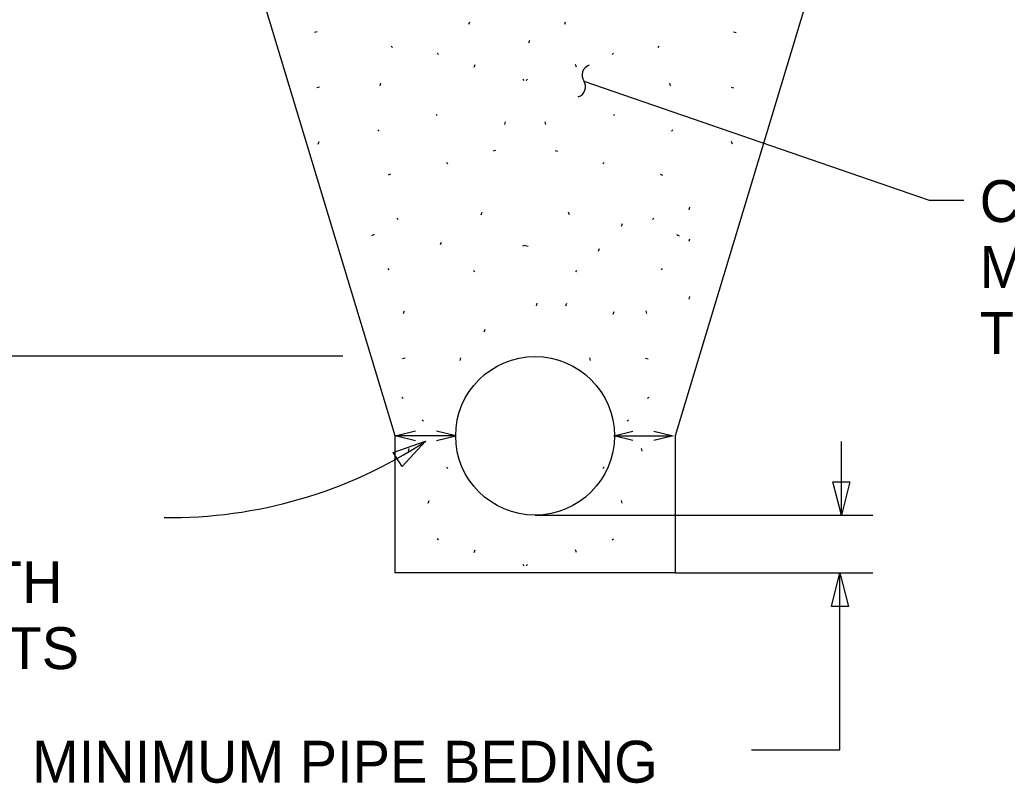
# Model space of a CAD drawing. Extents: x 9937.2 to 10006.2, y 10008.4 to 10068.3.
# Drawn here: x 9962.48 to 9987.09, y 10030.41 to 10049.44 of the extents above; entities that cross this region are included whole.
import ezdxf

# ---------------------------------------------------------------- set-up
doc = ezdxf.new("R2010")
doc.units = 0
for name, color, linetype in [('Default', 7, 'Continuous'), ('G-ANNO-TEXT', 7, 'Continuous'), ('G-ANNO-TTXT', 7, 'Continuous'), ('G-DETL-OTLN', 7, 'Continuous'), ('G-DETL-PATT', 7, 'Continuous')]:
    doc.layers.add(name, color=color, linetype=linetype)

# ---------------------------------------------------------------- blocks, each defined once
blk = doc.blocks.new('TERARR')
at = {"layer": 'Default'}
blk.add_lwpolyline([(-0.667, 0.167), (0, 0), (-0.667, -0.167)], close=True, dxfattribs=at)
blk = doc.blocks.new('TERBRK')
at = {"layer": 'Default'}
for centre, start, end in [((0.125, 0.167), 126.8699, 233.1301), ((-0.125, -0.167), 306.8699, 53.1301)]:
    blk.add_arc(centre, 0.208, start, end, dxfattribs=at)

msp = doc.modelspace()

# ---------------------------------------------------------------- linework, layer by layer
at = {"layer": 'Default'}
for p, q in [((9980.264, 10049.131), (9980.329, 10049.117)), ((9972.165, 10038.689), (9972.186, 10038.751)), ((9977.009, 10038.257), (9977.04, 10038.289))]:
    msp.add_line(p, q, dxfattribs=at)
at = {"layer": 'G-ANNO-TEXT'}
for p, q in [((9952.831, 10041.058), (9970.536, 10041.058)), ((9973.344, 10039.068), (9971.834, 10039.068)), ((9977.301, 10039.068), (9978.69, 10039.068)), ((9982.954, 10037.089), (9982.954, 10038.926)), ((9975.322, 10037.089), (9983.741, 10037.089)), ((9978.811, 10035.651), (9983.741, 10035.651)), ((9982.92, 10031.241), (9982.92, 10035.651)), ((9980.718, 10031.241), (9982.92, 10031.241))]:
    msp.add_line(p, q, dxfattribs=at)
for points in [[(9972.346, 10039.187), (9971.867, 10039.068), (9972.346, 10038.948)], [(9972.865, 10038.948), (9973.344, 10039.068), (9972.865, 10039.187)], [(9977.761, 10038.948), (9977.283, 10039.068), (9977.761, 10039.187)], [(9978.281, 10039.187), (9978.759, 10039.068), (9978.281, 10038.948)]]:
    msp.add_lwpolyline(points, dxfattribs=at)
msp.add_arc((9966.241, 10048.601), 11.569, 269.1889, 303.3244, dxfattribs=at)
at = {"layer": 'G-ANNO-TTXT'}
msp.add_lwpolyline([(9976.536, 10047.909), (9985.138, 10044.937), (9986.005, 10044.937)], dxfattribs=at)
at = {"layer": 'G-DETL-OTLN'}
msp.add_lwpolyline([(9984.004, 10056.263), (9978.811, 10039.068), (9978.811, 10035.651), (9971.834, 10035.651), (9971.834, 10039.068), (9966.641, 10056.263)], dxfattribs=at)
msp.add_circle((9975.322, 10039.068), 1.978, dxfattribs=at)
at = {"layer": 'G-DETL-PATT'}
for p, q in [((9973.673, 10049.322), (9973.694, 10049.385)), ((9976.063, 10049.322), (9976.084, 10049.385)), ((9969.894, 10049.131), (9969.829, 10049.117)), ((9975.167, 10048.86), (9975.188, 10048.923)), ((9971.772, 10048.743), (9971.74, 10048.774)), ((9978.386, 10048.743), (9978.418, 10048.774)), ((9972.915, 10048.567), (9972.883, 10048.599)), ((9977.243, 10048.567), (9977.275, 10048.599)), ((9973.805, 10048.258), (9973.826, 10048.321)), ((9976.353, 10048.258), (9976.332, 10048.321)), ((9975.054, 10047.924), (9975.023, 10047.955)), ((9975.104, 10047.924), (9975.135, 10047.955)), ((9969.953, 10047.756), (9969.888, 10047.742)), ((9971.461, 10047.79), (9971.482, 10047.853)), ((9978.697, 10047.79), (9978.676, 10047.853)), ((9980.205, 10047.756), (9980.27, 10047.742)), ((9972.885, 10047.047), (9972.854, 10047.078)), ((9977.273, 10047.047), (9977.304, 10047.078)), ((9971.437, 10046.661), (9971.406, 10046.692)), ((9974.567, 10046.825), (9974.588, 10046.888)), ((9975.591, 10046.825), (9975.57, 10046.888)), ((9978.721, 10046.661), (9978.752, 10046.692)), ((9969.919, 10046.338), (9969.94, 10046.401)), ((9980.239, 10046.338), (9980.218, 10046.401)), ((9974.338, 10046.177), (9974.274, 10046.163)), ((9975.82, 10046.177), (9975.884, 10046.163)), ((9973.149, 10045.848), (9973.118, 10045.879)), ((9977.009, 10045.848), (9977.04, 10045.879)), ((9971.721, 10045.592), (9971.658, 10045.561)), ((9978.437, 10045.592), (9978.5, 10045.561)), ((9979.16, 10044.703), (9979.181, 10044.765)), ((9971.909, 10044.461), (9971.878, 10044.493)), ((9973.981, 10044.574), (9974.002, 10044.637)), ((9976.177, 10044.574), (9976.156, 10044.637)), ((9978.249, 10044.461), (9978.28, 10044.493)), ((9977.476, 10044.295), (9977.497, 10044.358)), ((9971.311, 10044.084), (9971.248, 10044.053)), ((9978.847, 10044.084), (9978.91, 10044.053)), ((9979.16, 10043.915), (9979.181, 10043.977)), ((9972.967, 10043.833), (9972.988, 10043.896)), ((9975.071, 10043.809), (9975.006, 10043.795)), ((9975.087, 10043.809), (9975.152, 10043.795)), ((9976.905, 10043.67), (9976.926, 10043.733)), ((9971.689, 10043.205), (9971.658, 10043.236)), ((9978.469, 10043.205), (9978.5, 10043.236)), ((9973.823, 10043.158), (9973.792, 10043.189)), ((9976.335, 10043.158), (9976.366, 10043.189)), ((9979.16, 10042.474), (9979.181, 10042.537)), ((9975.357, 10042.311), (9975.378, 10042.374)), ((9976.091, 10042.311), (9976.112, 10042.374)), ((9972.047, 10042.117), (9972.068, 10042.18)), ((9977.268, 10042.099), (9977.289, 10042.162)), ((9978.111, 10042.117), (9978.09, 10042.18)), ((9974.054, 10041.659), (9974.075, 10041.722)), ((9972.082, 10041.002), (9972.017, 10040.988)), ((9973.453, 10040.948), (9973.474, 10041.011)), ((9976.705, 10040.948), (9976.684, 10041.011)), ((9978.076, 10041.002), (9978.141, 10040.988)), ((9972.035, 10040), (9972.004, 10040.031)), ((9978.123, 10040), (9978.154, 10040.031)), ((9972.539, 10039.434), (9972.508, 10039.466)), ((9977.619, 10039.434), (9977.65, 10039.466)), ((9977.993, 10038.689), (9977.972, 10038.751)), ((9973.149, 10038.257), (9973.118, 10038.289)), ((9972.662, 10037.392), (9972.683, 10037.455)), ((9977.496, 10037.392), (9977.475, 10037.455)), ((9972.915, 10036.474), (9972.883, 10036.505)), ((9977.243, 10036.474), (9977.275, 10036.505)), ((9973.805, 10036.164), (9973.826, 10036.227)), ((9976.353, 10036.164), (9976.332, 10036.227)), ((9975.054, 10035.83), (9975.023, 10035.862)), ((9975.104, 10035.83), (9975.135, 10035.862))]:
    msp.add_line(p, q, dxfattribs=at)

# ---------------------------------------------------------------- block references
at = {"layer": 'G-ANNO-TEXT'}
for p, xscale, yscale, rotation in [((9972.596, 10038.935), 1.2500000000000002, 1.2499999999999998, 33.32435277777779), ((9982.954, 10037.089), 1.25, 1.25, -90), ((9982.92, 10035.651), 1.25, 1.25, 90)]:
    msp.add_blockref('TERARR', p, dxfattribs=dict(at, xscale=xscale, yscale=yscale, rotation=rotation))
at = {"layer": 'G-ANNO-TTXT', "xscale": 1.25, "yscale": 1.25, "rotation": 160.94104016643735}
msp.add_blockref('TERBRK', (9976.536, 10047.909), dxfattribs=at)

# ---------------------------------------------------------------- texts
at = {"layer": 'G-ANNO-TEXT'}
for s, p in [('CLASS II GRANULAR', (9986.4, 10044.395)), ('MATERIAL COMPACTED', (9986.4, 10042.751)), ('TO 98% MAXIMUM DENSITY', (9986.4, 10041.107)), (' PIPE OR TO COMPLY WITH', (9944.932, 10034.9)), (' COMPACTION REQUIREMENTS', (9942.476, 10033.256)), ('MINIMUM PIPE BEDING ', (9962.788, 10030.426))]:
    msp.add_text(s, height=1.044, dxfattribs=at).set_placement(p)

doc.saveas('drawing.dxf')
